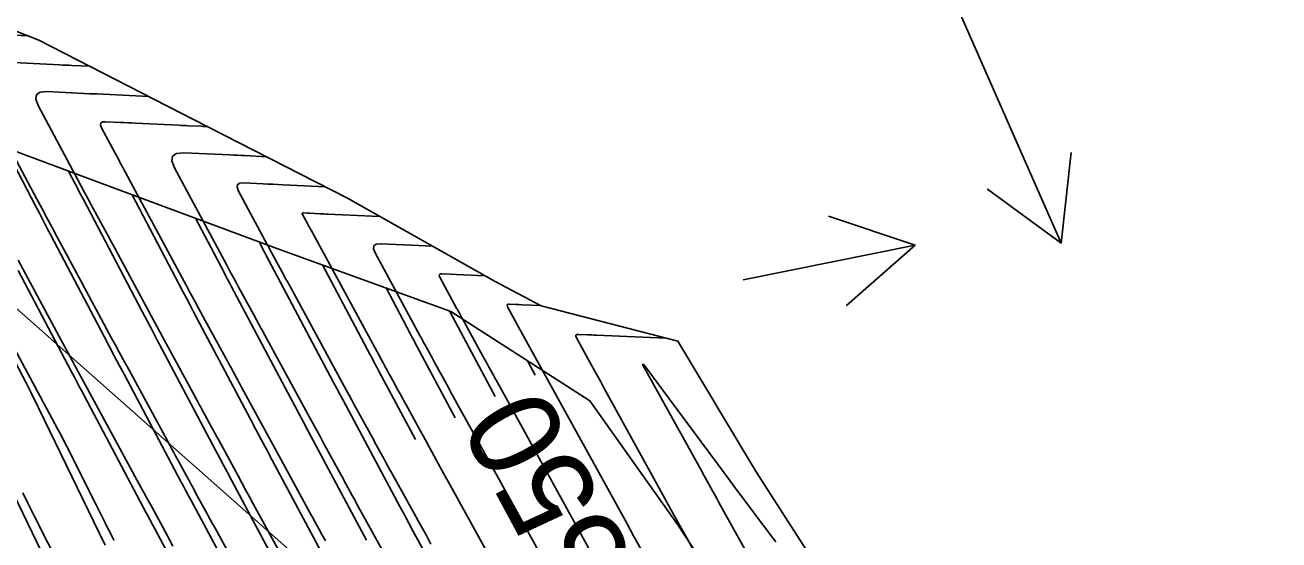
# Model space of a CAD drawing. Extents: x 954385 to 988206, y 1868364 to 1924553.
# Drawn here: x 957559.9 to 957642.4, y 1920301.8 to 1920335.7 of the extents above; entities that cross this region are included whole.
import ezdxf

# ---------------------------------------------------------------- set-up
doc = ezdxf.new("R2010")
doc.units = 0
for name, color, linetype in [('16', 7, 'Continuous'), ('24', 7, 'Continuous'), ('26', 7, 'Continuous'), ('6', 7, 'Continuous'), ('7', 7, 'Continuous')]:
    doc.layers.add(name, color=color, linetype=linetype)

msp = doc.modelspace()

# ---------------------------------------------------------------- linework, layer by layer
at = {"layer": '16'}
for points in [[(957450.815, 1920332.788), (957523.933, 1920382.247), (957528.249, 1920373.093), (957532.507, 1920363.9), (957536.678, 1920354.649), (957540.735, 1920345.321), (957544.536, 1920336.712), (957544.181, 1920336.46), (957544.363, 1920335.701), (957553.229, 1920329.626), (957564.727, 1920325.33), (957576.259, 1920321.058), (957587.884, 1920316.848), (957597.031, 1920310.962), (957602.817, 1920302.803), (957608.305, 1920294.443), (957613.907, 1920286.16), (957619.639, 1920277.964), (957625.387, 1920269.779), (957631.03, 1920261.523), (957636.615, 1920253.228), (957642.475, 1920245.119), (957647.904, 1920236.718)], [(957574.995, 1920296.511), (957570.758, 1920304.441), (957570.596, 1920304.743), (957570.435, 1920305.046), (957570.274, 1920305.348), (957570.114, 1920305.651), (957566.394, 1920312.67), (957566.06, 1920313.301), (957565.726, 1920313.933), (957565.393, 1920314.565), (957565.061, 1920315.198), (957561.551, 1920321.878), (957561.298, 1920322.359), (957561.046, 1920322.84), (957560.795, 1920323.322), (957560.544, 1920323.803), (957558.545, 1920327.64)], [(957577.337, 1920298.46), (957573.446, 1920305.741), (957573.183, 1920306.234), (957572.92, 1920306.727), (957572.658, 1920307.22), (957572.396, 1920307.713), (957568.865, 1920314.379), (957568.538, 1920314.996), (957568.211, 1920315.614), (957567.886, 1920316.232), (957567.56, 1920316.851), (957563.695, 1920324.208), (957563.613, 1920324.365), (957563.531, 1920324.521), (957563.449, 1920324.677), (957563.367, 1920324.834), (957562.718, 1920326.081)], [(957566.895, 1920324.527), (957570.246, 1920318.15), (957570.471, 1920317.722), (957570.696, 1920317.295), (957570.922, 1920316.868), (957571.148, 1920316.441), (957574.689, 1920309.757), (957575.047, 1920309.082), (957575.406, 1920308.408), (957575.765, 1920307.733), (957576.124, 1920307.06), (957579.678, 1920300.409)], [(957582.324, 1920301.789), (957582.02, 1920302.358), (957578.466, 1920309.009), (957578.178, 1920309.548), (957577.89, 1920310.088), (957577.603, 1920310.628), (957577.316, 1920311.169), (957573.43, 1920318.503), (957573.305, 1920318.739), (957573.181, 1920318.975), (957573.056, 1920319.212), (957572.931, 1920319.449), (957571.077, 1920322.978)], [(957589.318, 1920295.097), (957585.702, 1920301.807), (957585.408, 1920302.354), (957585.114, 1920302.901), (957584.82, 1920303.449), (957584.527, 1920303.996), (957580.807, 1920310.958), (957580.591, 1920311.363), (957580.375, 1920311.769), (957580.159, 1920312.175), (957579.944, 1920312.581), (957575.713, 1920320.565), (957575.689, 1920320.61), (957575.665, 1920320.656), (957575.641, 1920320.702), (957575.617, 1920320.747), (957575.259, 1920321.429)], [(957559.407, 1920319.548), (957562.917, 1920312.868), (957563.079, 1920312.56), (957563.241, 1920312.252), (957563.403, 1920311.945), (957563.566, 1920311.637), (957567.831, 1920303.589), (957567.89, 1920303.477), (957567.95, 1920303.364), (957568.01, 1920303.252), (957568.069, 1920303.14), (957572.653, 1920294.561)], [(957585.547, 1920308.419), (957583.149, 1920312.907), (957583.004, 1920313.178), (957582.86, 1920313.45), (957582.715, 1920313.721), (957582.571, 1920313.993), (957579.437, 1920319.907)], [(957565.126, 1920301.454), (957564.752, 1920302.222), (957564.378, 1920302.99), (957560.737, 1920310.493), (957560.713, 1920310.542), (957560.689, 1920310.592), (957560.237, 1920311.535), (957560.173, 1920311.667), (957560.108, 1920311.799), (957560.041, 1920311.93), (957559.973, 1920312.06), (957556.434, 1920318.797)], [(957583.614, 1920318.395), (957585.198, 1920315.405), (957585.271, 1920315.268), (957585.344, 1920315.13), (957585.417, 1920314.993), (957585.491, 1920314.856), (957588.175, 1920309.833)], [(957590.802, 1920311.247), (957587.832, 1920316.805), (957587.826, 1920316.817), (957587.791, 1920316.882)], [(957592.926, 1920313.604), (957593.43, 1920312.661)], [(957557.889, 1920307.293), (957561.535, 1920299.782)]]:
    msp.add_lwpolyline(points, dxfattribs=at)
at = {"layer": '24'}
msp.add_lwpolyline([(957549.482, 1920339.164), (957560.756, 1920334.717), (957570.908, 1920329.511), (957581.076, 1920324.316), (957590.795, 1920318.817), (957593.82, 1920317.217), (957602.826, 1920314.882), (957607.972, 1920306.291), (957613.378, 1920297.874), (957618.787, 1920289.46), (957622.216, 1920283.607), (957624.02, 1920280.927), (957629.264, 1920272.401), (957634.701, 1920264.006), (957640.225, 1920255.67), (957645.505, 1920247.168)], dxfattribs=at)
at = {"layer": '26'}
for points in [[(957607.131, 1920368.928), (957628.045, 1920321.35), (957623.207, 1920324.9), (957628.045, 1920321.35), (957628.7, 1920327.314)], [(957607.131, 1920318.928), (957618.431, 1920321.204), (957613.929, 1920317.237), (957618.431, 1920321.204), (957612.745, 1920323.119)], [(957557.131, 1920318.928), (957602.153, 1920279.081), (957596.274, 1920280.278), (957602.153, 1920279.081), (957600.25, 1920284.771)]]:
    msp.add_lwpolyline(points, dxfattribs=at)
at = {"layer": '6'}
for points in [[(957579.62, 1920301.747), (957579.539, 1920301.895), (957579.457, 1920302.043), (957579.376, 1920302.191), (957579.295, 1920302.339), (957578.971, 1920302.932), (957578.89, 1920303.081), (957578.809, 1920303.229), (957578.728, 1920303.377), (957578.647, 1920303.525), (957577.228, 1920306.116), (957576.965, 1920306.597), (957576.702, 1920307.078), (957576.439, 1920307.56), (957576.177, 1920308.042), (957574.122, 1920311.824), (957574.034, 1920311.986), (957573.945, 1920312.149), (957573.856, 1920312.312), (957573.768, 1920312.474), (957573.413, 1920313.125), (957573.324, 1920313.287), (957573.236, 1920313.45), (957573.147, 1920313.613), (957573.059, 1920313.775), (957571.578, 1920316.501), (957571.302, 1920317.009), (957571.027, 1920317.518), (957570.752, 1920318.027), (957570.477, 1920318.537), (957567.247, 1920324.536), (957566.951, 1920325.085), (957566.458, 1920326.001), (957566.359, 1920326.184), (957566.261, 1920326.368), (957566.162, 1920326.551), (957566.064, 1920326.735), (957564.893, 1920328.929), (957564.822, 1920329.116), (957564.842, 1920329.247), (957564.951, 1920329.321), (957565.151, 1920329.337), (957566.13, 1920329.29), (957566.374, 1920329.278), (957566.619, 1920329.267), (957566.864, 1920329.255), (957567.108, 1920329.243), (957569.985, 1920329.105), (957570.136, 1920329.098), (957570.287, 1920329.091), (957570.437, 1920329.084), (957570.588, 1920329.077), (957571.445, 1920329.037), (957571.589, 1920329.03), (957571.876, 1920329.016)], [(957590.126, 1920319.195), (957588.26, 1920319.28), (957587.849, 1920319.299), (957587.301, 1920319.324), (957587.189, 1920319.315), (957587.128, 1920319.273), (957587.117, 1920319.2), (957587.157, 1920319.096), (957588.284, 1920317.022), (957588.312, 1920316.97), (957588.341, 1920316.918), (957588.37, 1920316.865), (957588.398, 1920316.813), (957588.513, 1920316.604), (957588.542, 1920316.551), (957588.57, 1920316.499), (957588.599, 1920316.447), (957588.627, 1920316.394), (957589.986, 1920313.907), (957590.072, 1920313.748), (957590.159, 1920313.59), (957590.246, 1920313.432), (957590.333, 1920313.274), (957590.683, 1920312.641), (957590.77, 1920312.483), (957590.857, 1920312.325), (957590.944, 1920312.167), (957591.031, 1920312.009), (957597.073, 1920301.036)], [(957559.701, 1920304.894), (957559.967, 1920304.365), (957560.233, 1920303.836), (957560.499, 1920303.307), (957562.158, 1920300.003)]]:
    msp.add_lwpolyline(points, dxfattribs=at)
at = {"layer": '7'}
for points in [[(957554.992, 1920335.234), (957560.082, 1920334.983)], [(957564.13, 1920332.987), (957562.933, 1920333.044), (957562.734, 1920333.054), (957562.535, 1920333.064), (957562.335, 1920333.073), (957562.136, 1920333.083), (957559.088, 1920333.229)], [(957576.742, 1920300.785), (957574.877, 1920304.19), (957574.625, 1920304.65), (957574.374, 1920305.11), (957574.123, 1920305.571), (957573.872, 1920306.031), (957572.602, 1920308.369), (957572.486, 1920308.582), (957572.37, 1920308.796), (957572.253, 1920309.009), (957572.137, 1920309.222), (957571.672, 1920310.075), (957571.555, 1920310.289), (957571.439, 1920310.502), (957571.323, 1920310.715), (957571.207, 1920310.929), (957569.266, 1920314.503), (957568.904, 1920315.17), (957568.542, 1920315.838), (957568.182, 1920316.505), (957567.821, 1920317.173), (957565.98, 1920320.594), (957565.759, 1920321.003), (957565.539, 1920321.412), (957565.318, 1920321.822), (957565.098, 1920322.231), (957564.216, 1920323.868), (957563.996, 1920324.278), (957563.776, 1920324.687), (957563.557, 1920325.097), (957563.338, 1920325.507), (957560.719, 1920330.41), (957560.562, 1920330.829), (957560.606, 1920331.121), (957560.851, 1920331.285), (957561.297, 1920331.323), (957563.72, 1920331.206), (957564.149, 1920331.186), (957564.577, 1920331.165), (957565.005, 1920331.145), (957565.433, 1920331.124), (957568.003, 1920331.001)], [(957557.412, 1920330.268), (957560.611, 1920324.279), (957560.951, 1920323.643), (957561.292, 1920323.006), (957561.633, 1920322.371), (957561.975, 1920321.735), (957563.521, 1920318.864), (957563.775, 1920318.394), (957564.028, 1920317.923), (957564.282, 1920317.452), (957564.535, 1920316.981), (957565.549, 1920315.098), (957565.803, 1920314.627), (957566.057, 1920314.157), (957566.312, 1920313.687), (957566.567, 1920313.217), (957569.355, 1920308.082), (957569.499, 1920307.818), (957569.643, 1920307.554), (957569.786, 1920307.29), (957569.93, 1920307.026), (957570.507, 1920305.97), (957570.651, 1920305.707), (957570.794, 1920305.443), (957570.938, 1920305.179), (957571.082, 1920304.914), (957571.732, 1920303.717), (957571.889, 1920303.429), (957572.045, 1920303.142), (957572.202, 1920302.855), (957572.359, 1920302.568), (957574.837, 1920298.045)], [(957583.691, 1920300.561), (957581.808, 1920303.97), (957581.703, 1920304.161), (957581.598, 1920304.352), (957581.493, 1920304.543), (957581.388, 1920304.735), (957580.97, 1920305.5), (957580.866, 1920305.692), (957580.761, 1920305.883), (957580.657, 1920306.074), (957580.552, 1920306.265), (957579.462, 1920308.255), (957579.246, 1920308.65), (957579.03, 1920309.046), (957578.814, 1920309.442), (957578.598, 1920309.838), (957575.642, 1920315.278), (957575.581, 1920315.39), (957575.52, 1920315.502), (957575.459, 1920315.614), (957575.398, 1920315.726), (957575.154, 1920316.174), (957575.093, 1920316.286), (957575.032, 1920316.398), (957574.971, 1920316.51), (957574.91, 1920316.622), (957573.891, 1920318.498), (957573.701, 1920318.849), (957573.511, 1920319.199), (957573.322, 1920319.549), (957573.133, 1920319.9), (957569.681, 1920326.31), (957569.51, 1920326.761), (957569.556, 1920327.075), (957569.82, 1920327.252), (957570.3, 1920327.293), (957573.353, 1920327.15), (957573.592, 1920327.139), (957573.832, 1920327.127), (957574.072, 1920327.116), (957574.312, 1920327.105), (957575.75, 1920327.037)], [(957586.572, 1920301.527), (957586.289, 1920302.041), (957586.006, 1920302.554), (957585.722, 1920303.068), (957585.439, 1920303.581), (957583.996, 1920306.194), (957583.867, 1920306.428), (957583.738, 1920306.662), (957583.61, 1920306.896), (957583.482, 1920307.13), (957582.97, 1920308.068), (957582.842, 1920308.302), (957582.714, 1920308.537), (957582.585, 1920308.771), (957582.457, 1920309.005), (957581.696, 1920310.394), (957581.527, 1920310.704), (957581.357, 1920311.014), (957581.188, 1920311.324), (957581.02, 1920311.634), (957577.163, 1920318.733), (957577.129, 1920318.794), (957577.096, 1920318.856), (957577.062, 1920318.917), (957577.029, 1920318.978), (957576.895, 1920319.223), (957576.862, 1920319.285), (957576.828, 1920319.346), (957576.795, 1920319.407), (957576.762, 1920319.469), (957576.204, 1920320.496), (957576.1, 1920320.688), (957575.996, 1920320.879), (957575.892, 1920321.071), (957575.789, 1920321.263), (957573.899, 1920324.773), (957573.805, 1920325.02), (957573.83, 1920325.191), (957573.975, 1920325.289), (957574.237, 1920325.311), (957575.527, 1920325.251), (957575.849, 1920325.235), (957576.171, 1920325.22), (957576.494, 1920325.205), (957576.816, 1920325.19), (957579.623, 1920325.058)], [(957592.312, 1920297.296), (957588.058, 1920305.021), (957587.841, 1920305.416), (957587.623, 1920305.811), (957587.405, 1920306.206), (957587.187, 1920306.601), (957586.184, 1920308.417), (957586.031, 1920308.694), (957585.879, 1920308.971), (957585.727, 1920309.249), (957585.575, 1920309.526), (957584.91, 1920310.743), (957584.788, 1920310.967), (957584.666, 1920311.191), (957584.543, 1920311.415), (957584.421, 1920311.639), (957583.93, 1920312.534), (957583.808, 1920312.758), (957583.685, 1920312.982), (957583.563, 1920313.206), (957583.441, 1920313.43), (957578.683, 1920322.188), (957578.66, 1920322.23), (957578.619, 1920322.305), (957578.516, 1920322.494), (957578.498, 1920322.527), (957578.48, 1920322.56), (957578.462, 1920322.593), (957578.444, 1920322.627), (957578.116, 1920323.236), (957578.1, 1920323.279), (957578.104, 1920323.308), (957578.129, 1920323.325), (957578.175, 1920323.329), (957578.455, 1920323.316), (957578.623, 1920323.308), (957579.27, 1920323.278), (957579.397, 1920323.272), (957579.524, 1920323.266), (957579.65, 1920323.26), (957579.777, 1920323.254), (957582.694, 1920323.121), (957583.231, 1920323.097)], [(957594.692, 1920299.166), (957589.545, 1920308.515), (957589.392, 1920308.792), (957589.24, 1920309.068), (957589.087, 1920309.345), (957588.935, 1920309.621), (957588.324, 1920310.727), (957588.171, 1920311.004), (957588.019, 1920311.281), (957587.867, 1920311.558), (957587.716, 1920311.835), (957586.769, 1920313.569), (957586.693, 1920313.707), (957586.618, 1920313.845), (957586.542, 1920313.983), (957586.467, 1920314.121), (957586.164, 1920314.673), (957586.089, 1920314.812), (957586.013, 1920314.95), (957585.938, 1920315.088), (957585.863, 1920315.226), (957582.889, 1920320.698), (957582.783, 1920320.974), (957582.811, 1920321.167), (957582.972, 1920321.276), (957583.267, 1920321.302), (957585.284, 1920321.21), (957585.749, 1920321.189), (957586.678, 1920321.146)], [(957569.592, 1920301.403), (957569.344, 1920301.861), (957569.281, 1920301.975), (957569.219, 1920302.089), (957569.157, 1920302.204), (957569.094, 1920302.318), (957568.189, 1920303.977), (957568.018, 1920304.291), (957567.846, 1920304.606), (957567.675, 1920304.921), (957567.504, 1920305.235), (957563.837, 1920311.987), (957563.704, 1920312.231), (957563.572, 1920312.476), (957563.44, 1920312.72), (957563.308, 1920312.965), (957562.649, 1920314.188), (957562.386, 1920314.678), (957562.254, 1920314.922), (957559.404, 1920320.215)], [(957556.498, 1920319.316), (957560.997, 1920310.962), (957561.067, 1920310.832), (957561.087, 1920310.795), (957561.107, 1920310.758), (957561.994, 1920309.124), (957562.144, 1920308.845), (957562.292, 1920308.565), (957562.438, 1920308.283), (957562.581, 1920308.001), (957564.065, 1920305.043), (957564.299, 1920304.578), (957564.532, 1920304.113), (957565.121, 1920302.939), (957565.177, 1920302.828), (957565.232, 1920302.717), (957565.288, 1920302.606), (957565.344, 1920302.495), (957565.672, 1920301.843), (957565.686, 1920301.814), (957565.715, 1920301.756)], [(957593.779, 1920317.239), (957592.577, 1920317.293), (957592.364, 1920317.302), (957592.151, 1920317.312), (957591.725, 1920317.331), (957591.638, 1920317.324), (957591.591, 1920317.292), (957591.583, 1920317.235), (957591.614, 1920317.154), (957592.256, 1920315.979), (957592.277, 1920315.939), (957592.299, 1920315.899), (957592.321, 1920315.86), (957592.343, 1920315.82), (957592.43, 1920315.661), (957592.474, 1920315.582), (957592.518, 1920315.503), (957599.453, 1920302.907), (957599.931, 1920302.04), (957600.409, 1920301.175)], [(957603.96, 1920300.937), (957603.427, 1920301.896), (957602.894, 1920302.856), (957602.364, 1920303.816), (957601.834, 1920304.777), (957597.935, 1920311.859), (957597.742, 1920312.208), (957597.55, 1920312.557), (957597.357, 1920312.907), (957597.164, 1920313.256), (957596.145, 1920315.1), (957596.102, 1920315.209), (957596.113, 1920315.285), (957596.176, 1920315.328), (957596.292, 1920315.338), (957596.864, 1920315.313), (957597.006, 1920315.306), (957597.149, 1920315.3), (957597.292, 1920315.294), (957597.435, 1920315.287), (957602.044, 1920315.085)], [(957609.261, 1920301.668), (957608.958, 1920302.074), (957608.655, 1920302.48), (957608.353, 1920302.885), (957607.141, 1920304.508), (957606.838, 1920304.913), (957606.536, 1920305.319), (957606.234, 1920305.726), (957605.932, 1920306.132), (957600.688, 1920313.205), (957600.583, 1920313.347), (957600.578, 1920313.352), (957600.572, 1920313.356), (957600.566, 1920313.358), (957600.559, 1920313.359), (957600.507, 1920313.362), (957600.505, 1920313.361), (957600.505, 1920313.359), (957604.114, 1920306.827), (957604.241, 1920306.598), (957604.367, 1920306.369), (957604.494, 1920306.14), (957604.62, 1920305.911), (957605.125, 1920304.994), (957605.251, 1920304.765), (957605.378, 1920304.536), (957605.504, 1920304.307), (957605.632, 1920304.078), (957610.02, 1920296.197)]]:
    msp.add_lwpolyline(points, dxfattribs=at)

# ---------------------------------------------------------------- texts
at = {"layer": '16'}
msp.add_text('550', height=6, rotation=118.28545, dxfattribs=at).set_placement((957600.044, 1920300.403))

doc.saveas('drawing.dxf')
